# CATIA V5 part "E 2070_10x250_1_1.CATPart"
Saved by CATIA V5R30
Part number: E 2070_10x250_1_1
Definition: E 2070_10x250_1
Nomenclature: E 2070_10x250_1
Source: Unknown
Description: PART--DESC
Bounding box of the stored display mesh (mm): x 223.25 to 251.75, y -4.99 to 4.99, z 39.5 to 49.5
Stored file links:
  E:\Bakalarka\Model\Forma_v7\E 2070_10x250_1_1.CATPart
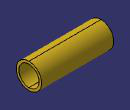
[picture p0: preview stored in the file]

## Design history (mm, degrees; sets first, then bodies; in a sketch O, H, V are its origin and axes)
Body1 "MANIFOLD_SOLID_BREP #156" (main body)
  Solid1: solid without history
  Pocket1: profile face of Solid1, direction along face of Solid1 reversed, length 221.5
